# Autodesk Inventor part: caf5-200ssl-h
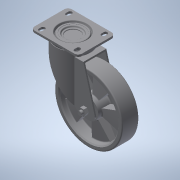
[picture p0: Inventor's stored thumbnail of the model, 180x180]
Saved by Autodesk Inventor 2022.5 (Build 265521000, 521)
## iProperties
Created: 2016-12
Part Number: caf5-200ssl-h
Material: 一般
Document SubType Name: Modeling
Designer: imaocorp
Density: 1 g/cm^3
Appearance: 既定
Author: imaocorp
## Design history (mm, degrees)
node "caf5-200ssl-h.x_t1"
node "caf5-200ssl-h"
node "Base1"
